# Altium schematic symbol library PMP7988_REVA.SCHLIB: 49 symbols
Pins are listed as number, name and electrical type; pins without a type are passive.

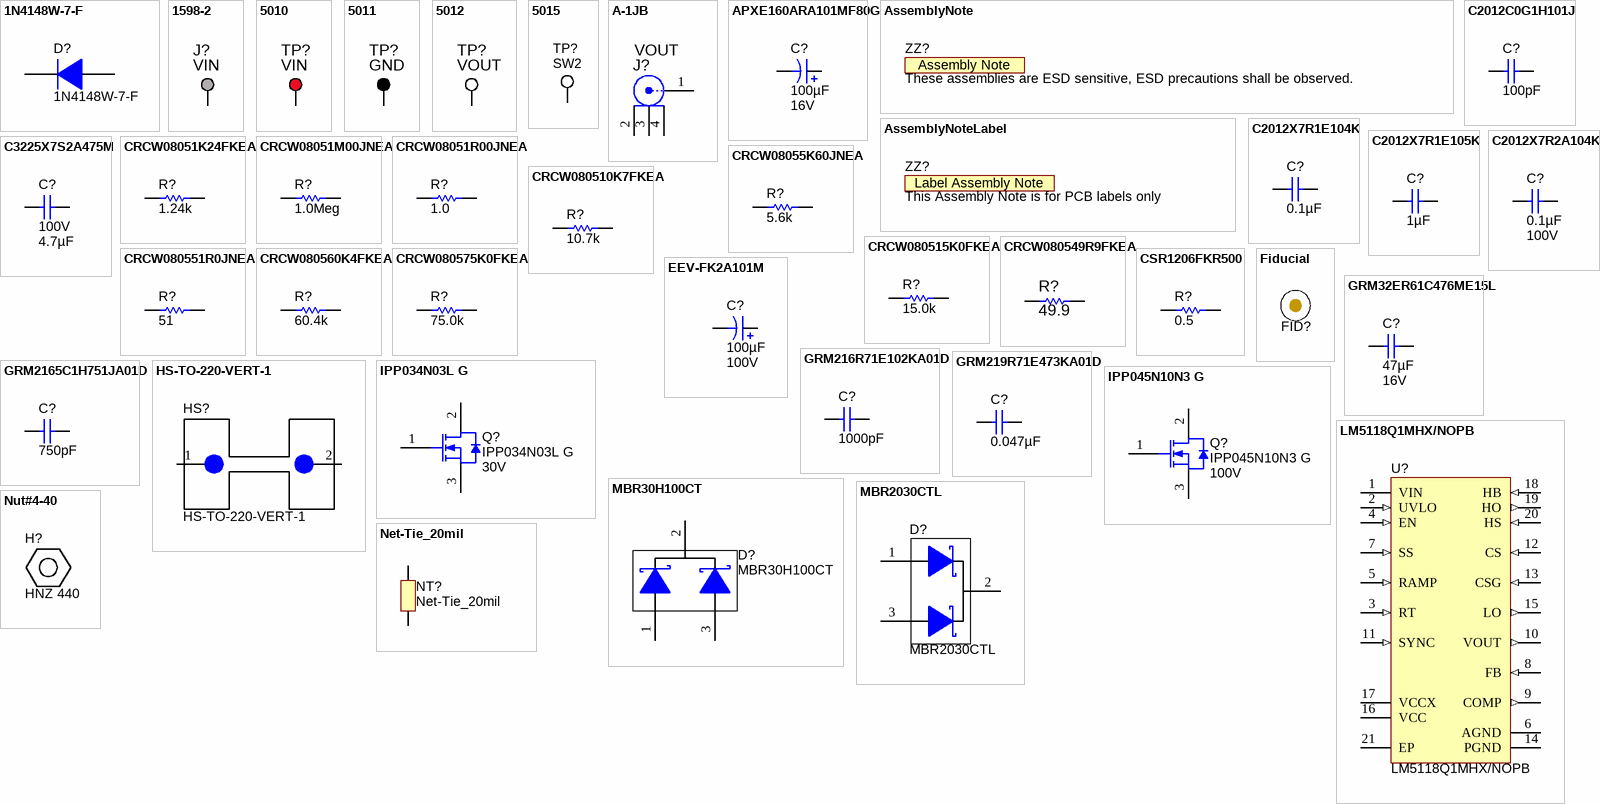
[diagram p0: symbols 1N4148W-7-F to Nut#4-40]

## 1N4148W-7-F
designator D?
Diode, Ultrafast, 100V, 0.15A, SOD-123; Manufacturer: Diodes Inc.; U/M: EA; Vf_V: 1.25; Io_A: 0.15; Vr_V: 100; TJmax_C: 150; Value: 1.25V
signal-integrity model Diode
simulation model 1N4148W
footprint SOD-123
pins: 1 K, 2 A

## 1598-2
designator J?, comment VIN
Terminal, Turret, TH, Triple; Manufacturer: Keystone; PartNumber: 1598-2; Alternate PartNumber: Equivalent; Alternate Manufacturer: Any; CompType: Turret Terminal; U/M: EA
footprint Keystone1598-2
pins: 1

## 5010
designator TP?, comment VIN
Test Point, TH, Multipurpose, Red; Manufacturer: Keystone; PartNumber: 5010; Alternate Manufacturer: Any; Alternate PartNumber: Equivalent; CompType: Test Point Loop; U/M: EA
footprint Keystone5010
pins: 1

## 5011
designator TP?, comment GND
Test Point, TH, Multipurpose, Black; Manufacturer: Keystone; PartNumber: 5011; Alternate Manufacturer: Any; Alternate PartNumber: Equivalent; CompType: Test Point Loop; U/M: EA
footprint Keystone5011
pins: 1

## 5012
designator TP?, comment VOUT
Test Point, TH, Multipurpose, White; Manufacturer: Keystone; PartNumber: 5012; Alternate Manufacturer: Any; Alternate PartNumber: Equivalent; CompType: Test Point Loop; U/M: EA
footprint Keystone5012
pins: 1

## 5015
designator TP?, comment SW2
Test Point, SMT, Miniature; PartNumber: 5015; Manufacturer: Keystone; CompType: Test Point Loop; U/M: EA
footprint Testpoint_Keystone_Miniature
pins: 1

## A-1JB
designator J?, comment VOUT
Connector, RF Jack, Vertical, Gold, SMD; Manufacturer: Amphenol; PartNumber: A-1JB; SymbolCreator: crossc; U/M: EA; Value: 50 ohm
signal-integrity model SI Model (SI Default Model)
footprint A-1JB (Amphenol recommended land pattern)
pins: 1, 2, 3, 4

## APXE160ARA101MF80G
designator C?  ValueDisplayed: 100µF  Value2: 16V  (hidden comment: APXE160ARA101MF80G)
CAP, AL, 100uF, 16V, +/-20%, 0.024 ohm, SMD; Manufacturer: Nippon Chemi-Con; Polarized: Y; CompType: Capacitor; U/M: EA; Cap_F: 0.0001; Tolerance_%: 20; VDC_V: 16; ESR_Ohm: 0.024; IRMS_A: 2.7; TaMin_C: -55; TaMax_C: 105; Cap_Case: F80
signal-integrity model Cap
simulation model Cap
footprint CAPSMT_62_F80
pins: 1 +, 2 -

## AssemblyNote
designator ZZ?, comment These assemblies are ESD sensitive, ESD precautions shall be observed.  (no BOM)
SymbolCreator: codlsc; CompType: AssemblyNote
footprint AssemblyNote

## AssemblyNoteLabel
designator ZZ?, comment This Assembly Note is for PCB labels only  (no BOM)
SymbolCreator: a0412235
footprint AssemblyNoteLabel

## C2012C0G1H101J
designator C?  ValueDisplayed: 100pF  (hidden comment: C2012C0G1H101J)
CAP, CERM, 100pF, 50V, +/-5%, C0G/NP0, 0805; Manufacturer: TDK; Polarized: N; CompType: Capacitor; U/M: EA; Cap_F: 0.0000000001; Tolerance_%: 5; VDC_V: 50; TaMin_C: -55; TaMax_C: 125; Cap_Case: 0805
signal-integrity model Cap
simulation model Cap
footprint 0805_HV
footprint 0805
footprint 0805M
footprint 0805L
pins: 1, 2

## C2012X7R1E104K
designator C?  ValueDisplayed: 0.1µF  (hidden comment: C2012X7R1E104K)
CAP, CERM, 0.1uF, 25V, +/-10%, X7R, 0805; Manufacturer: TDK; Polarized: N; CompType: Capacitor; U/M: EA; Cap_F: 0.0000001; Tolerance_%: 10; VDC_V: 25; TaMin_C: -55; TaMax_C: 125; Cap_Case: 0805
signal-integrity model Cap
simulation model Cap
footprint 0805_HV
footprint 0805
footprint 0805M
footprint 0805L
pins: 1, 2

## C2012X7R1E105K
designator C?  ValueDisplayed: 1µF  (hidden comment: C2012X7R1E105K)
CAP, CERM, 1uF, 25V, +/-10%, X7R, 0805; Manufacturer: TDK; Polarized: N; CompType: Capacitor; U/M: EA; Cap_F: 0.000001; Tolerance_%: 10; ESR_Ohm: 0.0075; Value1: 0.0075 ohm; VDC_V: 25; TaMin_C: -55; TaMax_C: 125; Cap_Case: 0805
signal-integrity model Cap
simulation model Cap
footprint 0805_HV
footprint 0805
footprint 0805M
footprint 0805L
pins: 1, 2

## C2012X7R2A104K
designator C?  ValueDisplayed: 0.1µF  Value2: 100V  (hidden comment: C2012X7R2A104K)
CAP, CERM, 0.1uF, 100V, +/-10%, X7R, 0805; Manufacturer: TDK; Polarized: N; CompType: Capacitor; U/M: EA; Cap_F: 0.0000001; Tolerance_%: 10; ESR_Ohm: 0.0158; Value1: 0.0158 ohm; VDC_V: 100; TaMin_C: -55; TaMax_C: 125; Cap_Case: 0805
signal-integrity model Cap
simulation model Cap
footprint 0805_HV
footprint 0805
footprint 0805M
footprint 0805L
pins: 1, 2

## C3225X7S2A475M
designator C?  Value2: 100V  ValueDisplayed: 4.7µF  (hidden comment: C3225X7S2A475M)
CAP, CERM, 4.7uF, 100V, +/-20%, X7S, 1210; Manufacturer: TDK; Polarized: N; CompType: Capacitor; U/M: EA; Cap_F: 0.0000047; Tolerance_%: 20; VDC_V: 100; TaMin_C: -55; TaMax_C: 125; Cap_Case: 1210
signal-integrity model Cap
simulation model Cap
footprint 1210 (1210 from SM-752 data)
footprint 1210M
footprint 1210L
pins: 1, 2

## CRCW08051K24FKEA
designator R?  value 1.24k  (hidden comment: CRCW08051K24FKEA)
RES, 1.24k ohm, 1%, 0.125W, 0805; Manufacturer: Vishay-Dale; CompType: Resistor; Res_ohm: 1240; Value_Code: 1k24; Tolerance_%: 1; Power_W: 0.125; VDC_V: 150; TempCo: 100 ppm/C; EIA_Code: E96; U/M: EA
signal-integrity model Resistor
simulation model Resistor
footprint 0805_HV
footprint 0805
footprint 0805M
footprint 0805L
pins: 1, 2

## CRCW08051M00JNEA
designator R?  value 1.0Meg  (hidden comment: CRCW08051M00JNEA)
RES, 1.0Meg ohm, 5%, 0.125W, 0805; Manufacturer: Vishay-Dale; CompType: Resistor; Res_ohm: 1000000; Value_Code: 1M00; Tolerance_%: 5; Power_W: 0.125; VDC_V: 150; TempCo: 200 ppm/C; EIA_Code: E24; U/M: EA
signal-integrity model Resistor
simulation model Resistor
footprint 0805_HV
footprint 0805
footprint 0805M
footprint 0805L
pins: 1, 2

## CRCW08051R00JNEA
designator R?  value 1.0  (hidden comment: CRCW08051R00JNEA)
RES, 1.0 ohm, 5%, 0.125W, 0805; Manufacturer: Vishay-Dale; CompType: Resistor; Res_ohm: 1; Value_Code: 1R00; Tolerance_%: 5; Power_W: 0.125; VDC_V: 150; TempCo: 200 ppm/C; EIA_Code: E24; U/M: EA
signal-integrity model Resistor
simulation model Resistor
footprint 0805_HV
footprint 0805
footprint 0805M
footprint 0805L
pins: 1, 2

## CRCW08055K60JNEA
designator R?  value 5.6k  (hidden comment: CRCW08055K60JNEA)
RES, 5.6k ohm, 5%, 0.125W, 0805; Manufacturer: Vishay-Dale; CompType: Resistor; Res_ohm: 5600; Value_Code: 5k60; Tolerance_%: 5; Power_W: 0.125; VDC_V: 150; TempCo: 200 ppm/C; EIA_Code: E24; U/M: EA
signal-integrity model Resistor
simulation model Resistor
footprint 0805_HV
footprint 0805
footprint 0805M
footprint 0805L
pins: 1, 2

## CRCW080510K7FKEA
designator R?  value 10.7k  (hidden comment: CRCW080510K7FKEA)
RES, 10.7k ohm, 1%, 0.125W, 0805; Manufacturer: Vishay-Dale; CompType: Resistor; Res_ohm: 10700; Value_Code: 10k7; Tolerance_%: 1; Power_W: 0.125; VDC_V: 150; TempCo: 100 ppm/C; EIA_Code: E96; U/M: EA
signal-integrity model Resistor
simulation model Resistor
footprint 0805_HV
footprint 0805
footprint 0805M
footprint 0805L
pins: 1, 2

## CRCW080515K0FKEA
designator R?  value 15.0k  (hidden comment: CRCW080515K0FKEA)
RES, 15.0k ohm, 1%, 0.125W, 0805; Manufacturer: Vishay-Dale; CompType: Resistor; Res_ohm: 15000; Value_Code: 15k0; Tolerance_%: 1; Power_W: 0.125; VDC_V: 150; TempCo: 100 ppm/C; EIA_Code: E96; U/M: EA
signal-integrity model Resistor
simulation model Resistor
footprint 0805_HV
footprint 0805
footprint 0805M
footprint 0805L
pins: 1, 2

## CRCW080549R9FKEA
designator R?  value 49.9  (hidden comment: CRCW080549R9FKEA)
RES, 49.9 ohm, 1%, 0.125W, 0805; Manufacturer: Vishay-Dale; Alternate PartNumber: Equivalent; Alternate Manufacturer: Any; CompType: Resistor; Value_Code: 49R9; Tolerance_%: 1; Power_W: 0.125; VDC_V: 150; TempCo: 100 ppm/C; EIA_Code: E96; U/M: EA
signal-integrity model Resistor
simulation model Resistor
footprint 0805_HV
footprint 0805
footprint 0805M
footprint 0805L
pins: 1, 2

## CRCW080551R0JNEA
designator R?  value 51  (hidden comment: CRCW080551R0JNEA)
RES, 51 ohm, 5%, 0.125W, 0805; Manufacturer: Vishay-Dale; CompType: Resistor; Value_Code: 51R0; Tolerance_%: 5; Power_W: 0.125; VDC_V: 150; TempCo: 200 ppm/C; EIA_Code: E24; U/M: EA
signal-integrity model Resistor
simulation model Resistor
footprint 0805_HV
footprint 0805
footprint 0805M
footprint 0805L
pins: 1, 2

## CRCW080560K4FKEA
designator R?  value 60.4k  (hidden comment: CRCW080560K4FKEA)
RES, 60.4k ohm, 1%, 0.125W, 0805; Manufacturer: Vishay-Dale; CompType: Resistor; Res_ohm: 60400; Value_Code: 60k4; Tolerance_%: 1; Power_W: 0.125; VDC_V: 150; TempCo: 100 ppm/C; EIA_Code: E96; U/M: EA
signal-integrity model Resistor
simulation model Resistor
footprint 0805_HV
footprint 0805
footprint 0805M
footprint 0805L
pins: 1, 2

## CRCW080575K0FKEA
designator R?  value 75.0k  (hidden comment: CRCW080575K0FKEA)
RES, 75.0k ohm, 1%, 0.125W, 0805; Manufacturer: Vishay-Dale; CompType: Resistor; Res_ohm: 75000; Value_Code: 75k0; Tolerance_%: 1; Power_W: 0.125; VDC_V: 150; TempCo: 100 ppm/C; EIA_Code: E96; U/M: EA
signal-integrity model Resistor
simulation model Resistor
footprint 0805_HV
footprint 0805
footprint 0805M
footprint 0805L
pins: 1, 2

## CSR1206FKR500
designator R?  value 0.5  (hidden comment: CSR1206FKR500)
RES, 0.5 ohm, 1%, 0.5W, 1206; Manufacturer: Stackpole Electronics Inc; CompType: Resistor; Value_Code: R500; Tolerance_%: 1; TempCo: 100 ppm/C; U/M: EA
signal-integrity model Resistor
simulation model Resistor
footprint 1206
footprint 1206M
footprint 1206L
pins: 1, 2

## EEV-FK2A101M
designator C?  ValueDisplayed: 100µF  Value2: 100V  (hidden comment: EEV-FK2A101M)
CAP, AL, 100uF, 100V, +/-20%, 0.17 ohm, SMD; Manufacturer: Panasonic; Polarized: Y; CompType: Capacitor; U/M: EA; Cap_F: 0.0001; Tolerance_%: 20; VDC_V: 100; ESR_Ohm: 0.17; IRMS_A: 0.793; TaMin_C: -55; TaMax_C: 105; Cap_Case: J16
signal-integrity model Cap
simulation model Cap
footprint SM_RADIAL_J16
pins: 1 +, 2 -

## Fiducial
designator FID?  (value not drawn)
Fiducial mark.  There is nothing to buy or mount.; SymbolCreator: codlsc
footprint Fiducial10-30
footprint Fiducial10-20
footprint Fiducial15-30
footprint Fiducial20-40
footprint Fiducial6.4-20
footprint Fiducial10-30_TopLayerKeepOutOnly
footprint Fiducial6.4-20_TopLayerKeepOutOnly
footprint Fiducial10-20_TopLayerKeepOutOnly
footprint Fiducial15-30_TopLayerKeepOutOnly
footprint Fiducial20-40_TopLayerKeepOutOnly

## GRM32ER61C476ME15L
designator C?  ValueDisplayed: 47µF  Value2: 16V  (hidden comment: GRM32ER61C476ME15L)
CAP, CERM, 47uF, 16V, +/-20%, X5R, 1210; Manufacturer: MuRata; Polarized: N; CompType: Capacitor; U/M: EA; Cap_F: 0.000047; Tolerance_%: 20; ESR_Ohm: 0.002; Value1: 0.002 ohm; VDC_V: 16; TaMin_C: -55; TaMax_C: 85; Cap_Case: 1210
signal-integrity model Cap
simulation model Cap
footprint 1210
footprint 1210M
footprint 1210L
pins: 1, 2

## GRM216R71E102KA01D
designator C?  ValueDisplayed: 1000pF  (hidden comment: GRM216R71E102KA01D)
CAP, CERM, 1000pF, 25V, +/-10%, X7R, 0805; Manufacturer: MuRata; Polarized: N; CompType: Capacitor; U/M: EA; Cap_F: 0.000000001; Tolerance_%: 10; VDC_V: 25; TaMin_C: -55; TaMax_C: 125; Cap_Case: 0805
signal-integrity model Cap
simulation model Cap
footprint 0805_HV
footprint 0805
footprint 0805M
footprint 0805L
pins: 1, 2

## GRM219R71E473KA01D
designator C?  ValueDisplayed: 0.047µF  (hidden comment: GRM219R71E473KA01D)
CAP, CERM, 0.047uF, 25V, +/-10%, X7R, 0805; Manufacturer: MuRata; Polarized: N; CompType: Capacitor; U/M: EA; Cap_F: 0.000000047; Tolerance_%: 10; VDC_V: 25; TaMin_C: -55; TaMax_C: 125; Cap_Case: 0805
signal-integrity model Cap
simulation model Cap
footprint 0805_HV
footprint 0805
footprint 0805M
footprint 0805L
pins: 1, 2

## GRM2165C1H751JA01D
designator C?  ValueDisplayed: 750pF  (hidden comment: GRM2165C1H751JA01D)
CAP, CERM, 750pF, 50V, +/-5%, C0G/NP0, 0805; Manufacturer: MuRata; Polarized: N; CompType: Capacitor; U/M: EA; Cap_F: 0.00000000075; Tolerance_%: 5; VDC_V: 50; TaMin_C: -55; TaMax_C: 125; Cap_Case: 0805
signal-integrity model Cap
simulation model Cap
footprint 0805_HV
footprint 0805
footprint 0805M
footprint 0805L
pins: 1, 2

## HS-TO-220-VERT-1
designator HS?
Heat Sink TO-220 Vertical 1 Inch; Manufacturer: AAVID Thermalloy; PartNumber: 529702B02500G; SymbolCreator: crossc; CompType: Hardware; U/M: EA
signal-integrity model SI Model (SI Default Model)
footprint HS-TO-220-VERT-1 (Heat Sink TO-220 Vertical 1 Inch)
pins: 1, 2

## IPP034N03L G
designator Q?  value 30V
MOSFET, N-CH, 30V, 80A, TO-220; Manufacturer: Infineon Technologies; Alternate Manufacturer: None; U/M: EA; ChType: N; VdsMax_V: 30; Value1: 0.0034 ohm; Rdson45_Ohm: 0.0038; Value2: 25 nC; QgTyp_nC: 25; Vgs_V: 20; IdsMax_A: 120
footprint TO-220AB (Footprint not found)
pins: 1 G, 2 D, 3 S

## IPP045N10N3 G
designator Q?  value 100V
MOSFET, N-CH, 100V, 100A, TO-220; Manufacturer: Infineon Technologies; Alternate Manufacturer: None; U/M: EA; ChType: N; VdsMax_V: 100; Value1: 0.0042 ohm; Rdson45_Ohm: 0.0042; Value2: 88 nC; QgTyp_nC: 155; Vgs_V: 20; IdsMax_A: 120
footprint TO-220AB (Copied from Altium's version of TO3B)
pins: 1 G, 2 D, 3 S

## LM5118Q1MHX/NOPB
designator U?
Wide Voltage Range Buck-Boost Controller, 20-pin TSSOP-EP, Pb-Free; Manufacturer: National Semiconductor; PackageTopMarking: NSUZXYTT*LM5118*Q1MH; PowerWise: N; CompType: Switcher
footprint MXA20A_N (TSOP, 20-Leads, Body 6.5x4.4mm, Pitch 0.65mm, Exposed Pad, IPC Medium Density)
footprint MXA20A_L (TSOP, 20-Leads, Body 6.5x4.4mm, Pitch 0.65mm, Exposed Pad, IPC High Density)
footprint MXA20A_M (TSOP, 20-Leads, Body 6.5x4.4mm, Pitch 0.65mm, Exposed Pad, IPC Low Density)
pins: 1 VIN (power), 2 UVLO (in), 3 RT (in), 4 EN (in), 5 RAMP (in), 6 AGND (power), 7 SS (in), 8 FB (in), 9 COMP (out), 10 VOUT (out), 11 SYNC (in), 12 CS (in), 13 CSG (in), 14 PGND (power), 15 LO (out), 16 VCC (power), 17 VCCX (power), 18 HB (in), 19 HO (out), 20 HS (in), 21 EP (power)

## MBR30H100CT
designator D?
Diode, Schottky, 100V, 30A, TO-220; Manufacturer: ON Semiconductor; Value: 0.8V; U/M: EA; Vf_V: 0.8; Io_A: 20; Vr_V: 100; TJmax_C: 150; RJC_CperW: 2
signal-integrity model Diode
simulation model mbrb20100ct
footprint TO-220AB (Copied from Altium's version of TO3B)
pins: 1 A, 2 K, 3 A

## MBR2030CTL
designator D?
Diode, Schottky, 30V, 20A, TO-220; Manufacturer: On Semiconductor; Value: 0.52V; U/M: EA; Vf_V: 0.52; Io_A: 15; Vr_V: 30; TJmax_C: 150; RJC_CperW: 3
signal-integrity model Diode
simulation model DI_MBRB1530CT
footprint TO-220AB (Copied from Altium's version of TO3B)
pins: 1 A, 2 K, 3 A

## Net-Tie_20mil
designator NT?  (net tie, no BOM)
Single point connection between nets.; SymbolCreator: crossc
footprint Net-Tie_20mil (20mil net tie, no solder mask opening, no solder paste)
pins: 1, 2

## Nut#4-40
designator H?, comment HNZ 440
HEX NUT 1/4" 4-40 100/PK; Manufacturer: B&F Fastener Supply; CompType: Hardware; Plating: Zinc

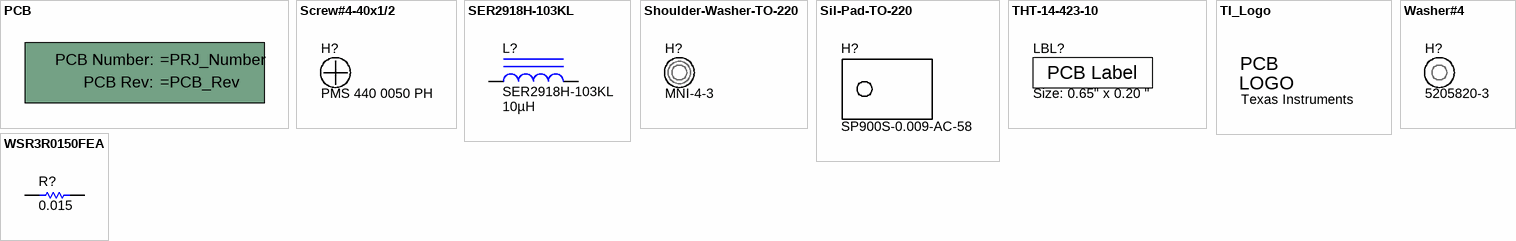
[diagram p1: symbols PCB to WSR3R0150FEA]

## PCB
designator !PCB?, comment Printed Circuit Board  (value not drawn)  (mechanical)
Manufacturer: Any; SymbolCreator: a0412235; CompType: PCB
1 alternate drawing of the same symbol

## Screw#4-40x1/2
designator H?, comment PMS 440 0050 PH
Machine Screw, Round, #4-40 x 1/2 Steel, Philips panhead; Manufacturer: B&F Fastener Supply; CompType: Hardware; U/M: EA; Description: MACHINE SCREW PAN PHILLIPS 4-40; Drive Type: Phillips; Thread Size: 4-40; Head Height: 0.075" (1.91mm); Plating: Zinc

## SER2918H-103KL
designator L?  ValueDisplayed: 10µH
Inductor, Shielded E Core, Ferrite, 10uH, 28A, 0.0026 ohm, SMD; Manufacturer: Coilcraft; Ind_H: 10.0E-6; Imax_A: 28; Irms: 28A @ 40C rise; Isat: 32.1A @ 30% inductance drop; DCR_ohm: 0.0026; U/M: EA
signal-integrity model Inductor
simulation model Inductor
footprint SER2918
pins: 1, 2

## Shoulder-Washer-TO-220
designator H?, comment MNI-4-3
WASHER SHOULDER #4 NYLON 25/PK; Manufacturer: Richco Plastic Co; CompType: Hardware

## Sil-Pad-TO-220
designator H?, comment SP900S-0.009-AC-58
THERM PAD TO-220 W/ADH .009" SP9; Manufacturer: Bergquist; CompType: Hardware; U/M: EA; Shape: Rectangular; Outline: 19.05mm x 12.70mm; Adhesive: Adhesive - One Side; Backing, Carrier: Fiberglass; Thermal Resistivity: 0.61°C/W; Thermal Conductivity: 1.6 W/m-K

## THT-14-423-10
designator LBL?, comment Size: 0.65" x 0.20 "
Thermal Transfer Printable Labels, 0.650" W x 0.200" H - 10,000 per roll; Manufacturer: Brady; PartNumber: THT-14-423-10; SymbolCreator: a0412235; CompType: Label
footprint Label_650x200

## TI_Logo
designator Logo?, comment Texas Instruments  (no BOM)
Texas Instrument Corporate Signature; SymbolCreator: codlsc
footprint TI_Stacked_SolderMask_Medium
footprint TI_Stacked_SolderMask_Small
footprint TI_Stacked_Overlay_Medium
footprint TI_Stacked_Overlay_Small
footprint TI_Horizontal_SolderMask_Medium
footprint TI_Horizontal_SolderMask_Small
footprint TI_Horizontal_Overlay_Medium
footprint TI_Horizontal_Overlay_Small
footprint TI_Symbol_SolderMask_Small
footprint TI_Symbol_Overlay_Medium
footprint TI_Symbol_Overlay_Small
footprint TI_Symbol_SolderMask_Medium

## Washer#4
designator H?, comment 5205820-3
WASHER FLAT #4 STEEL; Manufacturer: TE Connectivity; CompType: Hardware; Plating: Zinc, Clear Chromate

## WSR3R0150FEA
designator R?  value 0.015  (hidden comment: WSR3R0150FEA)
RES, 0.015 ohm, 1%, 3W, 4527; Manufacturer: Vishay-Dale; CompType: Resistor; Value_Code: R015; Tolerance_%: 1; Power_W: 3; TempCo: 75 ppm/C; EIA_Code: E96; U/M: EA
signal-integrity model Resistor
simulation model Resistor
footprint 4527
pins: 1, 2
